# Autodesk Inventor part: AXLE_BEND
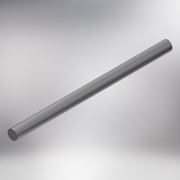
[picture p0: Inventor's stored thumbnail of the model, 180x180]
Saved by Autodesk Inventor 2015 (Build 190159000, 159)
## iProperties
Created: 2014-08
Part Number: AXLE_BEND
Material: Steel, Mild
Document SubType Name: Modeling
Designer: lakshayg
Density: 7.85 g/cm^3
Appearance: Semi-Polished
Mass: 180.404 g
Surface Area: 78.8665 cm^2
Volume: 22.9814 cm^3
Author: lakshayg
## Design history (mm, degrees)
sketch "Sketch1"
  geometry: C1 r 6 at (0, 0); 1 further point
  constraints: 1 centre point, 1 coincident
  dimensions: "d0" = 12 diameter of C1
extrude "Extrusion1" new body sketch "Sketch1" distance "d1" = 203.2; taper "d2" = 0 deg
node "Midplane"
body "Solid1"
